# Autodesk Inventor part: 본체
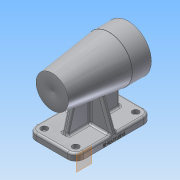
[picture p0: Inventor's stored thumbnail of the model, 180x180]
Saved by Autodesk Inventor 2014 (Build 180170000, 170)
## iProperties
Created: 2018-09
Part Number: 본체
Material: 알루미늄 6061
Document SubType Name: Modeling
Designer: Administrator
Density: 2.71 g/cm^3
Appearance: 알루미늄 - 평지
Mass: 703.596 g
Surface Area: 701.76 cm^2
Volume: 259.63 cm^3
Author: Administrator
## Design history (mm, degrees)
revolve "회전1" stored, may be unused: angle "d7" = 90 deg
sketch "스케치3"
  geometry: L1 (0, 0)-(0, 112); L2 (0, 112)-(-21, 112); L3 (-21, 112)-(-21, 97); L4 (-21, 97)-(-24, 97); L5 (-24, 97)-(-24, 43); L6 (-24, 43)-(-18, 43); L7 (-18, 43)-(-18, 31); L8 (-18, 31)-(-14.5, 31); L9 (-14.5, 31)-(-14.5, 13); L10 (-14.5, 13)-(-13, 13); L11 (-13, 13)-(-13, 9); L12 (-13, 9)-(-7.5, 9); L13 (-7.5, 9)-(-7.5, 6); L14 (-7.5, 6)-(0, 6)
  constraints: 28 end point, 10 parallel, 3 perpendicular, 1 point on line, 1 vertical
  dimensions: "d8" = 112 distance of L1.start L1.end; "d9" = 21 distance of L1.end L2.end; "d10" = 15 distance of L2.end L3.end; "d11" = 3 distance of L3.end L4.end; "d12" = 54 distance of L4.end L5.end; "d13" = 6 distance of L5.end L6.end; "d14" = 12 distance of L6.end L7.end; "d15" = 3.5 distance of L7.end L8.end; "d16" = 18 distance of L8.end L9.end; "d17" = 1.5 distance of L9.end L10.end; "d18" = 4 distance of L10.end L11.end; "d19" = 5.5 distance of L11.end L12.end; "d20" = 3 distance of L12.end L13.end
revolve "회전2" sketch "스케치3" stored, may be unused: angle "d21" = 90 deg
node "작업 평면1"
sketch "스케치4"
  geometry: L1 (0, 35)-(112, 35); L2 (112, 35)-(112, -35); L3 (112, -35)-(0, -35); L4 (0, -35)-(0, 35); 2 further points
  constraints: 8 end point, 2 parallel, 1 coincident, 1 horizontal, 1 midpoint, 1 perpendicular
  dimensions: "d23" = 112 distance of L2.end L3.end; "d24" = 70 distance of L1.end L2.end
extrude "돌출1" join sketch "스케치4" distance "d25" = 10; taper "d26" = 0 deg
node "작업 평면2"
sketch "스케치5"
  geometry: L1 (-64, 0)-(-64, 35); L2 (-64, 35)-(-21.714, 19.609); L3 (-29.258, 0)-(-64, 0); C1 r 26.301 at (0, 0) reference; C2 r 34 at (0, 0) reference; A1 r 29.258 centre (0, 0) between (-21.714, 19.609) and (-29.258, 0); 1 further point
  constraints: 6 end point, 2 point on circle, 1 centre point, 1 coincident, 1 perpendicular, 1 vertical
  dimensions: "d28" = 35 distance of L1.start L1.end; "d29" = 45 distance of L1.end L2.end; "d30" = 70 deg angle of L1 L2; "d31" = 64 distance of point (0, 0) L1.start; "d32" = 29.2576 radius of A1
extrude "돌출2" join sketch "스케치5" stored distance "d33" = 8; taper "d34" = 0 deg
node "작업 평면3"
fillet "모깎기2" dims "d47" = 3
fillet "모깎기3" dims "d48" = 3
fillet "모깎기4" dims "d49" = 12
fillet "모깎기5" dims "d50" = 3
sketch "스케치7"
  geometry: C1 r 4.75 at (-23, 12); C2 r 4.75 at (23, 12); A1 r 9 centre (23, 12) between (23, 3) and (32, 12) reference; A2 r 9 centre (-23, 12) between (-32, 12) and (-23, 3) reference; 1 further point
  constraints: 2 centre point, 2 coincident
  dimensions: "d51" = 9.5 diameter of C1; "d52" = 9.5 diameter of C2
extrude "돌출4" cut sketch "스케치7" distance "d53" = 5.4; taper "d54" = 0 deg
sketch "스케치8"
  geometry: C1 r 4.75 at (0, 0) reference; C2 r 2.75 at (0, 0); 1 further point
  constraints: 1 centre point, 1 coincident
  dimensions: "d55" = 5.5 diameter of C2
extrude "돌출5" cut sketch "스케치8" stored distance "d56" = 5.4; taper "d57" = 0 deg
sketch "스케치9"
  geometry: C1 r 4.75 at (0, 0) reference; C2 r 2.75 at (0, 0); 1 further point
  constraints: 1 centre point, 1 coincident
  dimensions: "d58" = 5.5 diameter of C2
extrude "돌출6" cut sketch "스케치9" stored distance "d59" = 5.4; taper "d60" = 0 deg
fillet "모깎기6" dims "d61" = 0.3
fillet "모깎기7" dims "d62" = 3
chamfer "모따기1" distance "d63" = 1; stored, may be unused: second distance "d64" = 2, angle "d65" = 45 deg
sketch "스케치10"
  geometry: L1 (74, -23)-(74, 23) reference; C1 r 34 at (0, 0) reference; 1 further point
  dimensions: "d66" = 26 distance of C1.centre point (0, 26); "d67" = 74 distance from line of L1 point (0, 26)
hole "구멍1" sketch "스케치10" at (0, 26) diameter "d68" = 3.242; stored, may be unused: countersink angle "d72" = 90 deg, drill point angle "d74" = 118 deg; dims "d69" = 8, "d70" = 4, "d71" = 2, "d73" = 11
node "작업 평면5"
sketch "스케치12"
  geometry: L1 (0, 0)-(0, 88) reference; L2 (0, 100)-(-7, 100) reference; 2 further points
  constraints: 1 other
  dimensions: "d78" = 3 distance from line of L1 point (-3, 44); "d79" = 56 distance from line of L2 point (-3, 44)
feature "엠보싱1" sketch "스케치12" dims "d0" = 112, "d1" = 34, "d2" = 28, "d8" = 112, "d9" = 21, "d10" = 15, "d11" = 3, "d12" = 54, "d13" = 6, "d14" = 12, "d15" = 3.5, "d16" = 18, "d17" = 1.5, "d18" = 4, "d19" = 5.5, "d20" = 3, "d80" = 0.5, "d81" = 0, "d91" = 7 deg, "d92" = 80
fillet "모깎기8" dims "d82" = 3
fillet "모깎기9" dims "d83" = 3
fillet "모깎기10" dims "d84" = 3
fillet "모깎기11" dims "d85" = 3
sketch "스케치13"
  geometry: L1 (-50.241, 0.598)-(-97.759, 0.598) reference; L2 (-49.497, 52)-(-49.497, 52) reference; L3 (-48.541, 60)-(-48.541, 60) reference; L4 (-40.022, 83.818)-(-107.978, 83.818) reference; L5 (-40, 112)-(-108, 112) reference; L6 (-108, 84.183)-(-40, 84.183) reference; L7 (-50.241, 0.598)-(-40.022, 83.818) reference; L8 (-40, 84.183)-(-40, 112) reference; L9 (-10, 0)-(-10, 18); L10 (-10, 18)-(-48.637, 28.353); L11 (-10, 96)-(-40, 96); L12 (-10, 18)-(-10, 96); L13 (-46.89, 27.885)-(-40, 84.183); 5 further points
  constraints: 10 end point, 3 point on line, 1 perpendicular, 6 other
  dimensions: "d93" = 64 distance of point (-74, 0) L9.start; "d94" = 18 distance of L9.start L9.end; "d96" = 105 deg angle of L10 L9; "d98" = 96 vertical distance of point (-74, 0) L11.start; "d99" = 78 distance of L9.end L11.start; "d100" = 17.40247 distance from line of L1 L9.end; "d101" = 25.36297 horizontal distance of point (-74, 0) L10.end; "d102" = 38.63703 horizontal distance of L9.end L10.end
extrude "돌출7" join sketch "스케치13" stored distance "d103" = 8; taper "d104" = 0 deg
fillet "모깎기14" dims "d105" = 3
fillet "모깎기15" dims "d106" = 3
node "솔리드1"
mirror "대칭1"
mirror "대칭2"
mirror "대칭3"
pattern_circular "원형 패턴1" dims angle "d76" = 360 deg
sketch "스케치2"
  geometry: L1 (0, 0)-(112, 0); L2 (112, 0)-(112, 34); L3 (112, 34)-(84, 34); L4 (84, 34)-(184, 34); L5 (84, 34)-(0.598, 23.759); A1 r 80 centre (80, 14) between (0.598, 23.759) and (1.235, 0)
  constraints: 10 end point, 2 horizontal, 2 point on circle, 1 centre point, 1 parallel, 1 perpendicular, 1 point on line
  dimensions: "d0" = 112 distance of L1.start L1.end; "d1" = 34 distance of L1.end L2.end; "d2" = 28 distance of L2.end L3.end; "d91" = 7 deg angle of L3 L5; "d92" = 80 radius of A1
node "투영된 루프1"
node "투영된 루프3"
node "투영된 루프4"
other parameters: "d22" = 74, "d27" = 56, "d89" = 173 deg
